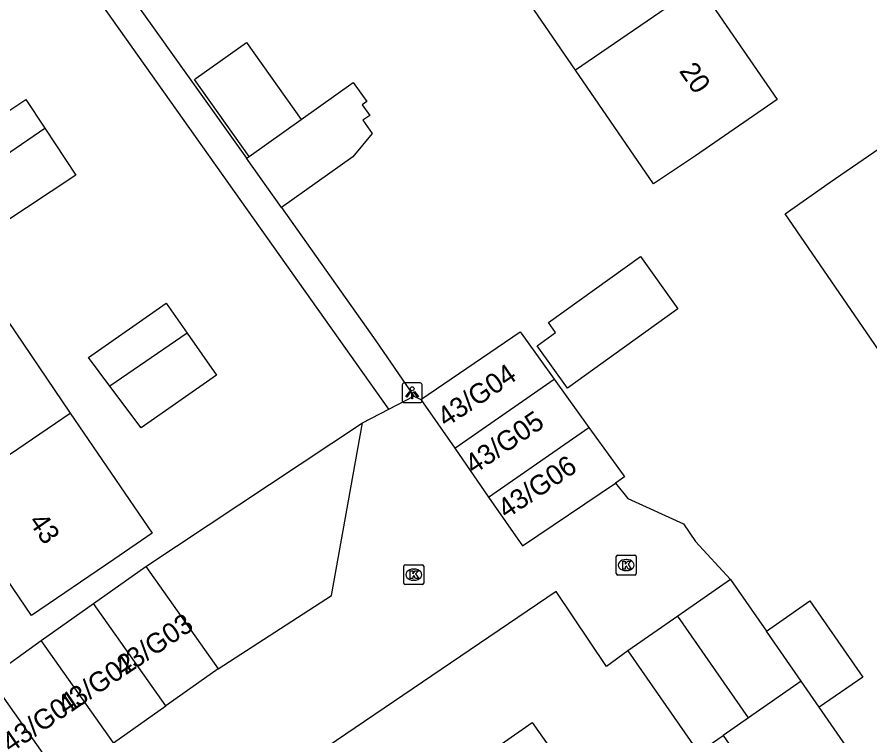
# Model space of a CAD drawing. Extents: x 157466 to 158888, y 383063 to 384677.
# Drawn here: x 158325.5 to 158368.41, y 383535.67 to 383571.85 of the extents above; entities that cross this region are included whole.
import ezdxf

# ---------------------------------------------------------------- set-up
doc = ezdxf.new("R2010")
doc.units = 0
for name, color, linetype in [('IMGEO_Groenvoorziening', 7, 'Continuous'), ('IMGEO_Kolk', 7, 'Continuous'), ('IMGEO_Lichtpunt', 7, 'Continuous'), ('IMGEO_Pand', 7, 'Continuous'), ('IMGEO_Pand_nummerreeks', 7, 'Continuous'), ('IMGEO_Rijbaan_lokaal_open', 7, 'Continuous'), ('IMGEO_Voetpad_open', 7, 'Continuous')]:
    doc.layers.add(name, color=color, linetype=linetype)

msp = doc.modelspace()

# ---------------------------------------------------------------- linework, layer by layer
at = {"layer": 'IMGEO_Groenvoorziening'}
msp.add_lwpolyline([(158331.976, 383544.199), (158342.883, 383551.43)], dxfattribs=at)
at = {"layer": 'IMGEO_Kolk'}
for p, q in [((158355.728, 383544.768), (158356.58, 383544.768)), ((158345.039, 383544.286), (158345.891, 383544.286)), ((158355.653, 383543.842), (158355.653, 383544.694)), ((158356.141, 383544.548), (158356.166, 383544.548)), ((158356.654, 383544.694), (158356.654, 383543.842)), ((158344.964, 383543.36), (158344.964, 383544.212)), ((158345.452, 383544.066), (158345.477, 383544.066)), ((158345.965, 383544.212), (158345.965, 383543.36)), ((158356.164, 383543.988), (158356.139, 383543.988)), ((158345.475, 383543.506), (158345.45, 383543.506)), ((158356.58, 383543.768), (158355.728, 383543.768)), ((158345.891, 383543.286), (158345.039, 383543.286))]:
    msp.add_line(p, q, dxfattribs=at)
for points in [[(158355.728, 383544.768), (158356.58, 383544.768)], [(158345.039, 383544.286), (158345.891, 383544.286)], [(158355.653, 383543.842), (158355.653, 383544.694)], [(158355.974, 383544.468), (158356.097, 383544.468), (158356.097, 383544.317), (158356.227, 383544.468), (158356.391, 383544.468), (158356.245, 383544.317), (158356.398, 383544.068), (158356.246, 383544.068), (158356.161, 383544.232), (158356.097, 383544.165), (158356.097, 383544.068), (158355.974, 383544.068), (158355.974, 383544.468)], [(158356.654, 383544.694), (158356.654, 383543.842)], [(158344.964, 383543.36), (158344.964, 383544.212)], [(158345.285, 383543.986), (158345.408, 383543.986), (158345.408, 383543.835), (158345.538, 383543.986), (158345.702, 383543.986), (158345.556, 383543.835), (158345.709, 383543.586), (158345.557, 383543.586), (158345.472, 383543.75), (158345.408, 383543.683), (158345.408, 383543.586), (158345.285, 383543.586), (158345.285, 383543.986)], [(158345.965, 383544.212), (158345.965, 383543.36)], [(158356.58, 383543.768), (158355.728, 383543.768)], [(158345.891, 383543.286), (158345.039, 383543.286)]]:
    msp.add_lwpolyline(points, dxfattribs=at)
for centre, start, end in [((158355.73, 383544.692), 91.552, 178.448), ((158355.73, 383544.692), 91.552, 178.448), ((158356.578, 383544.692), 1.552, 88.448), ((158356.578, 383544.692), 1.552, 88.448), ((158345.041, 383544.21), 91.552, 178.448), ((158345.041, 383544.21), 91.552, 178.448), ((158345.889, 383544.21), 1.552, 88.448), ((158345.889, 383544.21), 1.552, 88.448), ((158355.73, 383543.844), 181.552, 268.448), ((158355.73, 383543.844), 181.552, 268.448), ((158356.578, 383543.844), 271.552, 358.448), ((158356.578, 383543.844), 271.552, 358.448), ((158345.041, 383543.362), 181.552, 268.448), ((158345.041, 383543.362), 181.552, 268.448), ((158345.889, 383543.362), 271.552, 358.448), ((158345.889, 383543.362), 271.552, 358.448)]:
    msp.add_arc(centre, 0.0765, start, end, dxfattribs=at)
for centre, major_axis, ratio, start_param, end_param in [((158356.14, 383544.268), (-0.387, 0.002), 0.722429, 4.712389, 7.853982), ((158356.165, 383544.268), (-0.39, 0.002), 0.717154, 1.570796, 4.712389), ((158345.451, 383543.786), (-0.387, 0.002), 0.722429, 4.712389, 7.853982), ((158345.476, 383543.786), (-0.39, 0.002), 0.717154, 1.570796, 4.712389)]:
    msp.add_ellipse(centre, major_axis=major_axis, ratio=ratio, start_param=start_param, end_param=end_param, dxfattribs=at)
at = {"layer": 'IMGEO_Lichtpunt'}
for p, q in [((158344.883, 383553.346), (158344.883, 383552.539)), ((158344.883, 383553.346), (158344.883, 383552.539)), ((158345.785, 383553.441), (158344.977, 383553.441)), ((158345.785, 383553.441), (158344.977, 383553.441)), ((158345.879, 383552.539), (158345.879, 383553.346)), ((158345.879, 383552.539), (158345.879, 383553.346)), ((158344.977, 383552.445), (158345.785, 383552.445)), ((158344.977, 383552.445), (158345.785, 383552.445))]:
    msp.add_line(p, q, dxfattribs=at)
for points in [[(158345.257, 383553.01), (158345.296, 383552.982), (158345.108, 383552.72), (158345.07, 383552.747), (158345.257, 383553.01)], [(158345.359, 383552.962), (158345.406, 383552.962), (158345.406, 383552.64), (158345.359, 383552.64), (158345.359, 383552.962)], [(158345.469, 383552.982), (158345.507, 383553.009), (158345.694, 383552.747), (158345.655, 383552.719), (158345.469, 383552.982)]]:
    msp.add_lwpolyline(points, dxfattribs=at)
msp.add_circle((158345.382, 383553.144), 0.0994, dxfattribs=at)
for centre, start, end in [((158344.977, 383553.346), 90, 180), ((158344.977, 383553.346), 90, 180), ((158345.785, 383553.346), 0, 90), ((158345.785, 383553.346), 0, 90), ((158344.977, 383552.539), 180, 270), ((158344.977, 383552.539), 180, 270), ((158345.785, 383552.539), 270, 0), ((158345.785, 383552.539), 270, 360)]:
    msp.add_arc(centre, 0.0946, start, end, dxfattribs=at)
at = {"layer": 'IMGEO_Pand'}
for points in [[(158353.596, 383569.184), (158349.99, 383574.443)], [(158359.811, 383573.447), (158363.753, 383567.698), (158359.63, 383564.87), (158357.522, 383563.458), (158353.596, 383569.184)], [(158359.811, 383573.447), (158353.596, 383569.184)], [(158337.176, 383564.84), (158334.427, 383568.716), (158334.516, 383568.779), (158334.91, 383569.058), (158337.05, 383570.576), (158339.8, 383566.701)], [(158339.8, 383566.701), (158342.42, 383568.56), (158343.097, 383567.605), (158342.868, 383567.442), (158343.25, 383566.904), (158342.899, 383566.655), (158343.372, 383565.989), (158342.403, 383564.814), (158338.811, 383562.266)], [(158323.139, 383563.688), (158322.108, 383565.153), (158325.947, 383567.696), (158326.902, 383566.255)], [(158337.176, 383564.84), (158339.8, 383566.701)], [(158326.902, 383566.255), (158328.465, 383563.895), (158324.733, 383561.423), (158323.139, 383563.688)], [(158323.139, 383563.688), (158326.902, 383566.255)], [(158369.021, 383554.827), (158364.143, 383561.941), (158366.421, 383563.548), (158370.544, 383566.376), (158375.445, 383559.233)], [(158337.049, 383564.75), (158337.176, 383564.84)], [(158338.811, 383562.266), (158337.049, 383564.75)], [(158354.989, 383554.46), (158353.196, 383553.173), (158351.663, 383555.307), (158352.598, 383555.979), (158352.239, 383556.478), (158356.862, 383559.8), (158358.754, 383557.166), (158354.989, 383554.46)], [(158330.177, 383553.282), (158329.103, 383554.722), (158333.007, 383557.45), (158334.066, 383555.935)], [(158324.617, 383557.144), (158328.18, 383551.921)], [(158334.066, 383555.935), (158335.54, 383553.826), (158331.75, 383551.174), (158330.177, 383553.282)], [(158334.066, 383555.935), (158330.177, 383553.282)], [(158345.821, 383552.606), (158350.82, 383556.005), (158351.078, 383555.647), (158352.533, 383553.624)], [(158347.524, 383550.15), (158352.533, 383553.624)], [(158352.533, 383553.624), (158354.278, 383551.198)], [(158345.821, 383552.606), (158347.524, 383550.15)], [(158328.18, 383551.921), (158332.308, 383545.869), (158330.367, 383544.545), (158326.236, 383541.727), (158322.107, 383547.78)], [(158322.107, 383547.78), (158328.18, 383551.921)], [(158349.226, 383547.695), (158354.278, 383551.198)], [(158354.278, 383551.198), (158355.994, 383548.811), (158356.07, 383548.706), (158355.615, 383548.4)], [(158347.524, 383550.15), (158349.226, 383547.695)], [(158349.226, 383547.695), (158350.929, 383545.24), (158355.615, 383548.4)], [(158329.348, 383542.333), (158331.976, 383544.199)], [(158331.976, 383544.199), (158335.613, 383539.049)], [(158361.402, 383543.546), (158358.752, 383541.705)], [(158361.402, 383543.546), (158363.204, 383540.951)], [(158326.72, 383540.466), (158329.348, 383542.333)], [(158332.98, 383537.19), (158329.348, 383542.333)], [(158363.204, 383540.951), (158365.387, 383542.467), (158368.05, 383538.632), (158365.867, 383537.117)], [(158358.752, 383541.705), (158356.227, 383539.952)], [(158362.307, 383536.586), (158358.752, 383541.705)], [(158364.957, 383538.427), (158363.204, 383540.951)], [(158324.092, 383538.6), (158326.72, 383540.466)], [(158330.347, 383535.33), (158326.72, 383540.466)], [(158356.227, 383539.952), (158359.783, 383534.832), (158361.021, 383535.692)], [(158335.613, 383539.049), (158332.98, 383537.19)], [(158324.092, 383538.6), (158327.714, 383533.471)], [(158364.957, 383538.427), (158362.307, 383536.586)], [(158365.867, 383537.117), (158364.957, 383538.427)], [(158330.347, 383535.33), (158332.98, 383537.19)], [(158361.021, 383535.692), (158363.288, 383532.427), (158364.575, 383533.32), (158367.225, 383535.161), (158365.867, 383537.117)], [(158362.307, 383536.586), (158361.021, 383535.692)], [(158349.868, 383535.256), (158351.424, 383536.348), (158354.134, 383532.484), (158352.54, 383531.366)]]:
    msp.add_lwpolyline(points, dxfattribs=at)
at = {"layer": 'IMGEO_Rijbaan_lokaal_open'}
for points in [[(158344.206, 383552.119), (158345.465, 383552.774)], [(158345.465, 383552.774), (158345.821, 383552.606)], [(158342.883, 383551.43), (158344.206, 383552.119)], [(158335.613, 383539.049), (158341.323, 383542.746), (158342.883, 383551.43)], [(158355.615, 383548.4), (158356.238, 383547.619), (158359.035, 383546.353), (158359.64, 383545.449), (158361.402, 383543.546)], [(158356.227, 383539.952), (158355.151, 383539.165), (158352.622, 383542.94), (158336.26, 383531.831)]]:
    msp.add_lwpolyline(points, dxfattribs=at)
at = {"layer": 'IMGEO_Voetpad_open'}
for points in [[(158344.206, 383552.119), (158327.738, 383575.377), (158328.896, 383576.197), (158337.049, 383564.75)], [(158338.811, 383562.266), (158340.56, 383559.799), (158343.561, 383555.549), (158345.465, 383552.774)]]:
    msp.add_lwpolyline(points, dxfattribs=at)

# ---------------------------------------------------------------- texts
at = {"layer": 'IMGEO_Pand_nummerreeks'}
for s, rotation, p in [('20', 304.4411, (158358.789, 383569.137)), ('43/G04', 34.1031, (158347.084, 383551.178)), ('43/G05', 34.1031, (158348.474, 383548.809)), ('43/G06', 34.1031, (158350.122, 383546.569)), ('43', 304.298, (158326.057, 383546.461)), ('43/G03', 34.1031, (158330.824, 383538.613)), ('43/G02', 34.1031, (158327.948, 383536.665)), ('43/G01', 34.1031, (158325.173, 383534.787))]:
    msp.add_text(s, height=1, rotation=rotation, dxfattribs=at).set_placement(p)

doc.saveas('drawing.dxf')
